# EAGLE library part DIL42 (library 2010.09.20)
Dual In Line
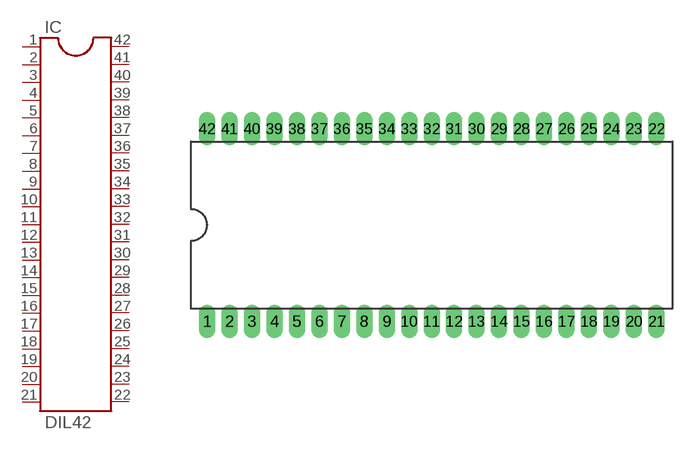
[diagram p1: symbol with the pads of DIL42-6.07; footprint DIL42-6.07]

Designator prefix IC

## DIL42-6.07  [DIL42-6.07]
1  1  pas
2  2  pas
3  3  pas
4  4  pas
5  5  pas
6  6  pas
7  7  pas
8  8  pas
9  9  pas
10  10  pas
11  11  pas
12  12  pas
13  13  pas
14  14  pas
15  15  pas
16  16  pas
17  17  pas
18  18  pas
19  19  pas
20  20  pas
21  21  pas
22  22  pas
23  23  pas
24  24  pas
25  25  pas
26  26  pas
27  27  pas
28  28  pas
29  29  pas
30  30  pas
31  31  pas
32  32  pas
33  33  pas
34  34  pas
35  35  pas
36  36  pas
37  37  pas
38  38  pas
39  39  pas
40  40  pas
41  41  pas
42  42  pas

## Footprint DIL42-6.07 (pad centres in mm)
Dual In Line Package 0.6 inch 0.07 pitch Drawn by D Lue Choy &micro; 2010.09.20
drill 0.813 long: 1 -17.78,-7.62; 2 -16.002,-7.62; 3 -14.224,-7.62; 4 -12.446,-7.62; 5 -10.668,-7.62; 6 -8.89,-7.62; 7 -7.112,-7.62; 8 -5.334,-7.62; 9 -3.556,-7.62; 10 -1.778,-7.62; 11 0,-7.62; 12 1.778,-7.62; 13 3.556,-7.62; 14 5.334,-7.62; 15 7.112,-7.62; 16 8.89,-7.62; 17 10.668,-7.62; 18 12.446,-7.62; 19 14.224,-7.62; 20 16.002,-7.62; 21 17.78,-7.62; 22 17.78,7.62; 23 16.002,7.62; 24 14.224,7.62; 25 12.446,7.62; 26 10.668,7.62; 27 8.89,7.62; 28 7.112,7.62; 29 5.334,7.62; 30 3.556,7.62; 31 1.778,7.62; 32 0,7.62; 33 -1.778,7.62; 34 -3.556,7.62; 35 -5.334,7.62; 36 -7.112,7.62; 37 -8.89,7.62; 38 -10.668,7.62; 39 -12.446,7.62; 40 -14.224,7.62; 41 -16.002,7.62; 42 -17.78,7.62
